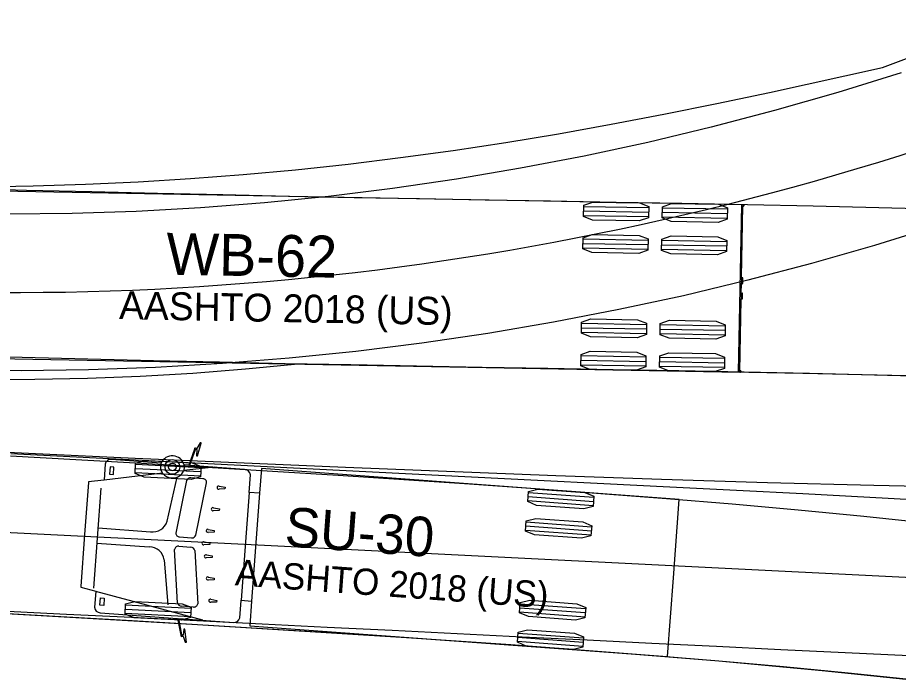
# Model space of a CAD drawing. Extents: x 260275 to 261282, y 610916 to 614143.
# Drawn here: x 260958.53 to 261003.29, y 612581.07 to 612614.79 of the extents above; entities that cross this region are included whole.
import ezdxf

# ---------------------------------------------------------------- set-up
doc = ezdxf.new("R2010")
doc.units = 0
doc.layers.add('TopoDOT_Transients', color=7, linetype='Continuous')

msp = doc.modelspace()

# ---------------------------------------------------------------- linework, layer by layer
at = {"layer": 'TopoDOT_Transients'}
for p, q in [((260987.302, 612605.198), (260990.602, 612605.138)), ((260991.301, 612605.126), (260994.601, 612605.066)), ((260995.314, 612605.282), (260995.159, 612596.783)), ((260987.294, 612604.74), (260990.593, 612604.68)), ((260987.298, 612604.969), (260990.597, 612604.909)), ((260991.293, 612604.667), (260994.593, 612604.607)), ((260991.297, 612604.897), (260994.597, 612604.836)), ((260987.268, 612603.32), (260990.567, 612603.26)), ((260987.272, 612603.549), (260990.572, 612603.489)), ((260991.271, 612603.476), (260994.571, 612603.416)), ((260987.264, 612603.09), (260990.563, 612603.03)), ((260991.263, 612603.018), (260994.563, 612602.958)), ((260991.267, 612603.247), (260994.567, 612603.187)), ((260995.317, 612601.562), (260995.312, 612601.297)), ((260995.302, 612600.772), (260995.312, 612601.295)), ((260995.307, 612601.031), (260995.236, 612601.033)), ((260995.302, 612600.766), (260995.297, 612600.5)), ((260987.194, 612599.266), (260990.494, 612599.206)), ((260987.186, 612598.808), (260990.485, 612598.748)), ((260987.19, 612599.037), (260990.489, 612598.977)), ((260991.189, 612598.964), (260994.489, 612598.904)), ((260991.193, 612599.193), (260994.493, 612599.133)), ((260991.185, 612598.735), (260994.485, 612598.675)), ((261025.504, 612585.252), (260776.884, 612597.696)), ((260987.164, 612597.616), (260990.464, 612597.556)), ((260991.163, 612597.544), (260994.463, 612597.484)), ((260987.156, 612597.158), (260990.455, 612597.098)), ((260987.16, 612597.387), (260990.459, 612597.327)), ((260991.155, 612597.085), (260994.455, 612597.025)), ((260991.159, 612597.314), (260994.459, 612597.254)), ((260965.819, 612592.153), (260963.304, 612592.338)), ((260964.527, 612592.1), (260967.857, 612591.933)), ((260965.898, 612591.647), (260962.923, 612591.298)), ((260963.235, 612591.967), (260963.207, 612591.589)), ((260963.428, 612591.952), (260963.235, 612591.967)), ((260963.401, 612591.575), (260963.428, 612591.952)), ((260964.507, 612591.684), (260967.836, 612591.517)), ((260964.517, 612591.892), (260967.846, 612591.725)), ((260968.514, 612591.954), (260966.976, 612591.774)), ((260963.207, 612591.589), (260963.401, 612591.575)), ((260966.13, 612589.203), (260966.643, 612591.448)), ((260967.123, 612591.268), (260966.574, 612588.607)), ((260967.95, 612591.359), (260967.335, 612591.405)), ((260962.77, 612590.893), (260962.395, 612585.802)), ((260967.59, 612588.502), (260968.138, 612591.163)), ((260969.071, 612590.852), (260968.769, 612590.838)), ((260968.78, 612590.992), (260969.077, 612590.934)), ((260969.077, 612590.934), (260969.071, 612590.852)), ((260970.3, 612590.665), (260969.897, 612585.188)), ((260970.831, 612590.626), (260970.427, 612585.149)), ((260984.475, 612590.461), (260987.799, 612590.216)), ((260984.49, 612590.668), (260987.815, 612590.424)), ((260968.489, 612589.893), (260968.785, 612589.835)), ((260984.46, 612590.253), (260987.784, 612590.008)), ((260968.779, 612589.753), (260968.477, 612589.739)), ((260968.785, 612589.835), (260968.779, 612589.753)), ((260984.365, 612588.965), (260987.689, 612588.72)), ((260984.38, 612589.173), (260987.705, 612588.928)), ((260962.62, 612588.862), (260965.281, 612588.666)), ((260968.515, 612588.652), (260968.213, 612588.638)), ((260968.225, 612588.792), (260968.521, 612588.734)), ((260968.521, 612588.734), (260968.515, 612588.652)), ((260984.35, 612588.757), (260987.674, 612588.512)), ((260962.564, 612588.098), (260965.225, 612587.902)), ((260966.762, 612588.411), (260967.377, 612588.366)), ((260968.009, 612588.158), (260968.305, 612588.1)), ((260968.305, 612588.1), (260968.299, 612588.018)), ((260966.665, 612585.058), (260966.512, 612587.771)), ((260966.727, 612587.937), (260967.342, 612587.892)), ((260967.533, 612587.725), (260967.685, 612585.013)), ((260968.299, 612588.018), (260967.998, 612588.004)), ((260965.986, 612587.246), (260966.164, 612584.962)), ((260968.42, 612587.359), (260968.118, 612587.345)), ((260968.129, 612587.499), (260968.426, 612587.441)), ((260968.426, 612587.441), (260968.42, 612587.359)), ((260968.215, 612586.372), (260968.525, 612586.314)), ((260968.525, 612586.314), (260968.519, 612586.232)), ((260968.519, 612586.232), (260968.204, 612586.218)), ((260967.941, 612584.175), (260962.507, 612585.643)), ((260962.717, 612584.937), (260962.745, 612585.314)), ((260962.91, 612584.922), (260962.717, 612584.937)), ((260962.745, 612585.314), (260962.938, 612585.3)), ((260962.938, 612585.3), (260962.91, 612584.922)), ((260964.02, 612584.951), (260967.35, 612584.785)), ((260968.647, 612585.102), (260968.345, 612585.088)), ((260968.357, 612585.242), (260968.653, 612585.184)), ((260968.653, 612585.184), (260968.647, 612585.102)), ((260984.074, 612585.017), (260987.398, 612584.772)), ((260964, 612584.535), (260967.329, 612584.369)), ((260964.01, 612584.743), (260967.339, 612584.577)), ((260967.47, 612584.846), (260966.855, 612584.892)), ((260984.043, 612584.602), (260987.368, 612584.357)), ((260984.059, 612584.809), (260987.383, 612584.564)), ((260983.949, 612583.313), (260987.273, 612583.068)), ((260983.964, 612583.521), (260987.288, 612583.276)), ((260983.933, 612583.106), (260987.258, 612582.861))]:
    msp.add_line(p, q, dxfattribs=at)
for points in [[(260911.385, 612607.632), (260922.039, 612607.21), (260932.691, 612606.819), (260943.342, 612606.462), (260953.993, 612606.15), (260956.658, 612606.184), (260959.324, 612606.244), (260961.99, 612606.332), (260964.656, 612606.454), (260967.323, 612606.613), (260969.991, 612606.814), (260972.66, 612607.058), (260975.329, 612607.346), (260977.999, 612607.674), (260980.67, 612608.042), (260983.343, 612608.449), (260986.018, 612608.892), (260988.694, 612609.369), (260991.374, 612609.879), (260994.059, 612610.418), (260996.748, 612610.983), (261002.487, 612612.256), (261003.848, 612612.757)], [(261003.431, 612611.985), (261000.216, 612610.99), (260996.999, 612610.069), (260993.778, 612609.223), (260990.552, 612608.452), (260987.32, 612607.755), (260984.082, 612607.132), (260980.838, 612606.583), (260977.59, 612606.109), (260974.337, 612605.708), (260971.081, 612605.381), (260967.822, 612605.127), (260964.561, 612604.946), (260961.3, 612604.839), (260958.04, 612604.805)], [(260995.384, 612605.258), (260995.384, 612605.281), (260947.463, 612606.153), (260947.386, 612601.903), (260947.308, 612597.654), (260995.23, 612596.782), (260995.23, 612596.804)], [(261005.639, 612605.034), (261002.301, 612605.125), (260998.963, 612605.203), (260995.626, 612605.273), (260992.29, 612605.337), (260988.955, 612605.397), (260985.621, 612605.456), (260982.289, 612605.516), (260978.958, 612605.577), (260975.628, 612605.64), (260972.298, 612605.707), (260968.969, 612605.777), (260965.641, 612605.852), (260962.312, 612605.93), (260958.984, 612606.013), (260955.656, 612606.101)], [(260995.382, 612601.293), (260995.387, 612601.56), (260995.387, 612601.561), (260995.317, 612601.562), (260995.317, 612601.598), (260995.383, 612605.233), (260995.384, 612605.234)], [(261005.232, 612604.199), (261002.072, 612603.212), (260998.873, 612602.293), (260995.64, 612601.443), (260992.377, 612600.663), (260989.086, 612599.953), (260985.772, 612599.314), (260982.436, 612598.747), (260979.083, 612598.253), (260975.714, 612597.831), (260972.332, 612597.484), (260968.939, 612597.211), (260965.538, 612597.013), (260962.13, 612596.89), (260958.718, 612596.842), (260955.304, 612596.87)], [(260995.231, 612596.828), (260995.231, 612596.829), (260995.297, 612600.464), (260995.298, 612600.5), (260995.367, 612600.499), (260995.368, 612600.5), (260995.373, 612600.767)], [(261003.728, 612596.585), (260998.439, 612596.713), (260972.791, 612597.178), (260970.113, 612596.922), (260967.436, 612596.717), (260964.759, 612596.562), (260962.082, 612596.455), (260959.407, 612596.397), (260956.732, 612596.387), (260954.059, 612596.425), (260951.386, 612596.511), (260948.716, 612596.644), (260938.041, 612597.354), (260927.368, 612598.004), (260919.365, 612598.455), (260908.692, 612598.918)], [(261005.384, 612596.537), (261002.085, 612596.628), (260998.775, 612596.706), (260995.457, 612596.775), (260992.132, 612596.838), (260988.803, 612596.898), (260985.471, 612596.958), (260982.136, 612597.017), (260978.8, 612597.078), (260975.462, 612597.142), (260972.124, 612597.209), (260968.785, 612597.279), (260965.446, 612597.354), (260962.107, 612597.433), (260958.767, 612597.516), (260955.428, 612597.604)], [(260900.569, 612595.515), (260943.182, 612593.414), (260964.509, 612592.414), (260975.188, 612591.95), (260985.89, 612591.53), (260991.256, 612591.343), (260996.637, 612591.176), (261002.039, 612591.033), (261007.472, 612590.914)], [(260967.592, 612592.858), (260967.637, 612592.855), (260967.637, 612592.855), (260967.622, 612592.537), (260967.622, 612592.535), (260967.678, 612592.531), (260967.679, 612592.534), (260967.866, 612593.178), (260967.866, 612593.181), (260967.802, 612593.185), (260967.649, 612592.901), (260967.648, 612592.901), (260967.601, 612592.903)], [(261005.24, 612590.231), (261001.835, 612590.413), (260998.442, 612590.591), (260995.059, 612590.766), (260991.684, 612590.939), (260988.316, 612591.111), (260984.954, 612591.281), (260981.597, 612591.451), (260978.245, 612591.62), (260974.896, 612591.788), (260971.55, 612591.956), (260968.207, 612592.124), (260964.866, 612592.292), (260961.528, 612592.459), (260958.19, 612592.626)], [(260967.525, 612592.869), (260967.525, 612592.868), (260967.238, 612592.055), (260967.226, 612592.049), (260966.999, 612592.066)], [(260970.071, 612591.84), (260967.304, 612592.043), (260967.292, 612592.049), (260967.571, 612592.848), (260967.571, 612592.848)], [(261004.883, 612589.094), (261001.538, 612589.444), (260998.194, 612589.767), (260994.852, 612590.065), (260991.51, 612590.343), (260988.171, 612590.604), (260984.833, 612590.851), (260981.496, 612591.085), (260978.16, 612591.309), (260974.825, 612591.525), (260971.491, 612591.733), (260968.158, 612591.934), (260964.826, 612592.13), (260961.494, 612592.322), (260958.163, 612592.51)], [(260962.983, 612592.108), (260962.923, 612591.302), (260962.918, 612591.298), (260962.138, 612591.206), (260962.133, 612591.165), (260961.939, 612588.528), (260961.745, 612585.892), (260961.744, 612585.849), (260962.502, 612585.645), (260962.506, 612585.64), (260962.447, 612584.834)], [(260969.831, 612584.291), (260969.897, 612585.185), (260969.901, 612585.188), (260970.426, 612585.149), (260970.426, 612585.138), (260970.335, 612583.899), (260991.564, 612582.335), (260991.858, 612586.324), (260992.152, 612590.313), (260970.923, 612591.877), (260970.831, 612590.637), (260970.83, 612590.626), (260970.304, 612590.665), (260970.301, 612590.669), (260970.366, 612591.562)], [(261004.659, 612581.071), (260999.422, 612581.614), (260994.161, 612582.095), (260988.884, 612582.526), (260983.594, 612582.919), (260978.296, 612583.283), (260967.681, 612583.949), (260957.051, 612584.56), (260935.769, 612585.699), (260893.177, 612587.866)], [(261003.838, 612582.372), (261000.584, 612582.524), (260997.32, 612582.679), (260994.045, 612582.837), (260990.763, 612582.997), (260987.474, 612583.158), (260984.179, 612583.321), (260980.879, 612583.485), (260977.575, 612583.649), (260974.267, 612583.814), (260970.957, 612583.979), (260967.643, 612584.144), (260964.327, 612584.31), (260961.01, 612584.476), (260957.69, 612584.642)], [(261004.01, 612581.142), (261000.737, 612581.485), (260997.454, 612581.801), (260994.163, 612582.095), (260990.866, 612582.369), (260987.564, 612582.627), (260984.257, 612582.872), (260980.947, 612583.104), (260977.634, 612583.327), (260974.318, 612583.541), (260971.001, 612583.748), (260967.681, 612583.948), (260964.361, 612584.144), (260961.039, 612584.335), (260957.716, 612584.523)], [(260962.731, 612584.559), (260966.653, 612584.27), (260966.664, 612584.263), (260966.829, 612583.417), (260966.829, 612583.416)], [(260966.878, 612583.429), (260966.877, 612583.429), (260966.718, 612584.261), (260966.731, 612584.264), (260969.497, 612584.061)], [(260966.899, 612583.37), (260966.946, 612583.366), (260966.946, 612583.366), (260967.056, 612583.062), (260967.121, 612583.057), (260967.121, 612583.06), (260967.03, 612583.724), (260967.029, 612583.727), (260966.974, 612583.731), (260966.973, 612583.729), (260966.941, 612583.413), (260966.941, 612583.413), (260966.897, 612583.416)]]:
    msp.add_lwpolyline(points, dxfattribs=at)
for points in [[(260987.293, 612604.683), (260987.303, 612605.255), (260987.768, 612605.419), (260990.144, 612605.376), (260990.603, 612605.195), (260990.592, 612604.623), (260990.127, 612604.459), (260987.752, 612604.503)], [(260991.292, 612604.611), (260991.302, 612605.182), (260991.768, 612605.346), (260994.143, 612605.303), (260994.602, 612605.122), (260994.592, 612604.551), (260994.126, 612604.387), (260991.751, 612604.43)], [(260987.263, 612603.034), (260987.273, 612603.606), (260987.738, 612603.769), (260990.114, 612603.726), (260990.573, 612603.545), (260990.562, 612602.974), (260990.097, 612602.81), (260987.721, 612602.853)], [(260991.262, 612602.961), (260991.272, 612603.533), (260991.738, 612603.697), (260994.113, 612603.653), (260994.572, 612603.473), (260994.561, 612602.901), (260994.096, 612602.737), (260991.721, 612602.78)], [(260987.185, 612598.751), (260987.195, 612599.323), (260987.66, 612599.487), (260990.036, 612599.444), (260990.495, 612599.263), (260990.484, 612598.691), (260990.019, 612598.527), (260987.644, 612598.57)], [(260991.184, 612598.678), (260991.195, 612599.25), (260991.66, 612599.414), (260994.035, 612599.371), (260994.494, 612599.19), (260994.484, 612598.618), (260994.018, 612598.454), (260991.643, 612598.498)], [(260987.155, 612597.101), (260987.165, 612597.673), (260987.63, 612597.837), (260990.006, 612597.794), (260990.465, 612597.613), (260990.454, 612597.041), (260989.989, 612596.877), (260987.614, 612596.921)], [(260991.154, 612597.028), (260991.164, 612597.6), (260991.63, 612597.764), (260994.005, 612597.721), (260994.464, 612597.54), (260994.454, 612596.968), (260993.988, 612596.805), (260991.613, 612596.848)], [(260964.504, 612591.632), (260964.53, 612592.152), (260965.004, 612592.285), (260967.401, 612592.164), (260967.859, 612591.985), (260967.833, 612591.465), (260967.359, 612591.332), (260964.962, 612591.452)], [(260984.456, 612590.201), (260984.494, 612590.72), (260984.971, 612590.842), (260987.365, 612590.666), (260987.819, 612590.475), (260987.78, 612589.956), (260987.303, 612589.835), (260984.91, 612590.011)], [(260984.346, 612588.705), (260984.384, 612589.224), (260984.861, 612589.346), (260987.254, 612589.17), (260987.708, 612588.979), (260987.67, 612588.461), (260987.193, 612588.339), (260984.8, 612588.515)], [(260963.997, 612584.483), (260964.023, 612585.003), (260964.497, 612585.136), (260966.894, 612585.016), (260967.352, 612584.836), (260967.326, 612584.317), (260966.852, 612584.184), (260964.455, 612584.304)], [(260984.04, 612584.55), (260984.078, 612585.069), (260984.555, 612585.191), (260986.948, 612585.014), (260987.402, 612584.824), (260987.364, 612584.305), (260986.887, 612584.183), (260984.494, 612584.36)], [(260983.929, 612583.054), (260983.968, 612583.573), (260984.445, 612583.695), (260986.838, 612583.518), (260987.292, 612583.328), (260987.254, 612582.809), (260986.777, 612582.687), (260984.383, 612582.864)]]:
    msp.add_lwpolyline(points, close=True, dxfattribs=at)
for centre, radius in [((260995.418, 612605.246), 0.0266), ((260995.264, 612596.816), 0.0266), ((260966.398, 612591.965), 0.374), ((260966.398, 612591.965), 0.193)]:
    msp.add_circle(centre, radius, dxfattribs=at)
for centre, radius, start, end in [((260958.205, 612750.824), 150, 267.13462, 294.9182), ((260995.418, 612605.246), 0.0363, 198.718, 159.8806), ((260995.347, 612601.294), 0.0354, 3.249, 175.4344), ((260995.347, 612601.294), 0.0352, 178.3553, 358.9418), ((260995.337, 612600.767), 0.0352, 358.973, 179.5595), ((260995.337, 612600.767), 0.0352, 178.745, 1.3844), ((260995.265, 612596.816), 0.0363, 198.0342, 159.1969), ((260967.564, 612592.885), 0.0418, 26.2794, 203.2943), ((260967.564, 612592.891), 0.0434, 279.6997, 310.3725), ((260963.26, 612592.06), 0.282, 81.1584, 170.2378), ((260966.312, 612591.971), 0.526, 159.7314, 217.9774), ((260966.393, 612591.898), 0.628, 15.5395, 156.0312), ((260966.395, 612592.033), 0.629, 217.8318, 266.5211), ((260966.485, 612591.958), 0.524, 318.0452, 11.8453), ((260970.047, 612591.518), 0.323, 7.9378, 85.7862), ((260966.41, 612592.033), 0.63, 265.141, 317.5438), ((260967.308, 612591.214), 0.193, 81.7293, 163.6438), ((260967.954, 612591.175), 0.184, 356.3788, 91.2501), ((260968.756, 612590.904), 0.091, 74.1028, 168.2666), ((260968.757, 612590.928), 0.0909, 183.2701, 277.5053), ((260968.464, 612589.806), 0.091, 74.1028, 168.2666), ((260968.465, 612589.829), 0.0909, 183.2701, 277.5053), ((260965.391, 612589.431), 0.773, 261.8116, 342.8958), ((260966.758, 612588.595), 0.184, 176.3844, 271.2445), ((260968.2, 612588.705), 0.091, 74.1028, 168.2666), ((260968.201, 612588.729), 0.0909, 183.2701, 277.5053), ((260967.405, 612588.556), 0.193, 261.7244, 343.6487), ((260967.984, 612588.071), 0.091, 74.1028, 168.2666), ((260967.986, 612588.094), 0.091, 183.3058, 277.4697), ((260965.222, 612587.129), 0.773, 8.6767, 89.7608), ((260966.696, 612587.755), 0.184, 80.3279, 175.1881), ((260967.342, 612587.699), 0.193, 7.9237, 89.8481), ((260968.104, 612587.412), 0.0909, 74.0671, 168.3023), ((260968.106, 612587.436), 0.091, 183.3058, 277.4697), ((260968.204, 612586.284), 0.0909, 74.0671, 168.3023), ((260968.206, 612586.308), 0.091, 183.3058, 277.4697), ((260966.856, 612585.084), 0.193, 187.9286, 269.8431), ((260967.501, 612585.028), 0.184, 260.3224, 355.1936), ((260968.332, 612585.155), 0.0909, 74.0671, 168.3023), ((260968.334, 612585.178), 0.091, 183.3058, 277.4697), ((260962.729, 612584.841), 0.282, 181.3346, 270.414), ((260969.521, 612584.382), 0.323, 265.7862, 343.6346), ((260966.864, 612583.394), 0.0418, 148.2781, 325.2931), ((260966.864, 612583.388), 0.0434, 41.1999, 71.8727)]:
    msp.add_arc(centre, radius, start, end, dxfattribs=at)

# ---------------------------------------------------------------- texts
for s, height, rotation, p in [('WB-62', 2.125, 358.9574, (260966.073, 612601.733)), ('AASHTO 2018 (US)', 1.41667, 358.9574, (260963.679, 612599.474)), ('SU-30', 2, 355.7862, (260972.066, 612587.942)), ('AASHTO 2018 (US)', 1.33333, 355.7862, (260969.556, 612585.955))]:
    msp.add_text(s, height=height, rotation=rotation, dxfattribs=at).set_placement(p)

doc.saveas('drawing.dxf')
